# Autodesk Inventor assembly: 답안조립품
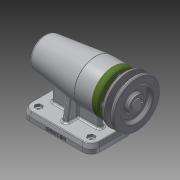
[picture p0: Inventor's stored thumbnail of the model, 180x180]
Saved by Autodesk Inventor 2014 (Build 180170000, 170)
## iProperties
Created: 2017-01
Part Number: 답안조립품
Document SubType Name: Assembly
Designer: owner
Author: owner
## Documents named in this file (12)
- C:\Users\owner\Desktop\470107V1007\답안조립품.iam
- C:\Users\owner\Desktop\470107V1007\본체.ipt
- C:\Users\owner\Desktop\470107V1007\베어링 51202.ipt
- C:\Users\owner\Desktop\470107V1007\어댑터슬리브.ipt
- C:\Users\owner\Desktop\470107V1007\베어링 6004.ipt
- C:\Users\owner\Desktop\470107V1007\축.ipt
- C:\Users\owner\Desktop\470107V1007\볼트 M4 x 12.ipt
- C:\Users\owner\Desktop\470107V1007\커버.ipt
- C:\Users\owner\Desktop\470107V1007\오일 실.ipt
- C:\Users\owner\Desktop\470107V1007\키 5 x 5 x 16.ipt
- C:\Users\owner\Desktop\470107V1007\V벨트풀리.ipt
- C:\Users\owner\Desktop\470107V1007\멈춤나사 M3x8.ipt
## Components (6 placed, 2 different names)
1. ISO 4762 M4 x 12:1
2. V벨트풀리:1 — 각도:1
3. ISO 4762 M4 x 12:2
4. ISO 4762 M4 x 12:3
5. ISO 4762 M4 x 12:4
6. ISO 4762 M4 x 12:5
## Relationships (1: Angle 1)
- 각도:1 [Angle]: V벨트풀리:1
